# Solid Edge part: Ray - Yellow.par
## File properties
Author: hhakima
Template: Normal.par
Last saved by: hhakima
Revision: 8
Application: Solid Edge
Accuracy: 0.990
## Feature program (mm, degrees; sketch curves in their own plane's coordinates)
sketch for "unnamed Protrusion 1" plane through (0, 0, 0) normal (0, -1, 0) x-axis (1, 0, 0)
  circle centre (0, 0) radius 1.2
extrude "unnamed Protrusion 1" add finite 10.6 along -normal
sketch for "ExtrudedProtrusion_2" plane through (0, 0, 1.2) normal (1, 0, 0) x-axis (0, 1, 0)
extrude "ExtrudedProtrusion_2" add finite 66 along +normal
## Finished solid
Body 1: solid body, 7 faces, 10 edges, 5 vertices.
  Faces by surface: plane 5, cylinder 2
  Edges by curve: circle 5, intersection 3, line 2
Bounding box of the edges (mm): 67.200 x 10.600 x 2.500, from (-1.2, 0, -1.25) to (66, 10.6, 1.25).
Cylindrical faces by radius (mm): R1.2 x1, R1.25 x1
Planar faces by outward normal: +x 1, +y 1, -x 2, -y 1
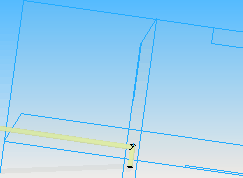
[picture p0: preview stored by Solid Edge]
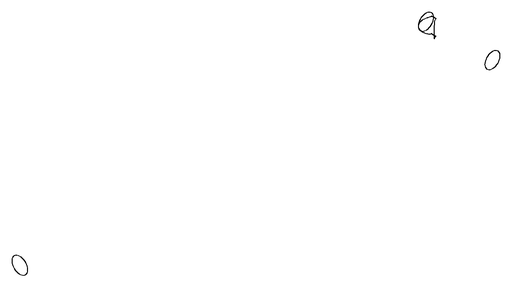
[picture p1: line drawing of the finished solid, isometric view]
